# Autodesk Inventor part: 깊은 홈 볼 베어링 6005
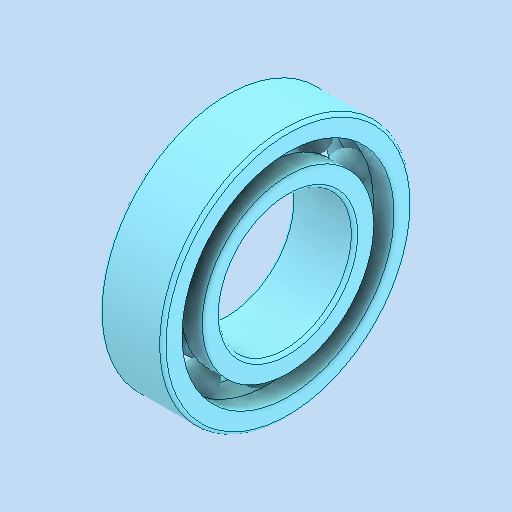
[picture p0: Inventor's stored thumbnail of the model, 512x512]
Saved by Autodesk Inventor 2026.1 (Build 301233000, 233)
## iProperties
Created: 2025-11
Part Number: 깊은 홈 볼 베어링 6005
Material: 강철, 연강
Description: 깊은 그루브 볼 베어링
Document SubType Name: Modeling
Designer: PC-30
Density: 7.85 g/cm^3
Appearance: 기본값
Author: jhkim
Sending System: Autodesk Inventor 2026
Preprocessor: ST-DEVELOPER v20.1
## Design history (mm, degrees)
feature "Solid1"
feature "Solid1:1"
feature "Solid1:2"
feature "Solid1:3"
feature "Solid1:4"
feature "Solid1:5"
feature "Solid1:6"
feature "Solid1:7"
feature "Solid1:8"
feature "Solid1:9"
feature "Solid1:10"
feature "Solid1:11"
node "솔리드1"
node "솔리드2"
node "솔리드3"
node "솔리드4"
node "솔리드5"
node "솔리드6"
node "솔리드7"
node "솔리드8"
node "솔리드9"
node "솔리드10"
node "솔리드11"
node "솔리드12"
